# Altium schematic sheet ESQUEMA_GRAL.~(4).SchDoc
size A3
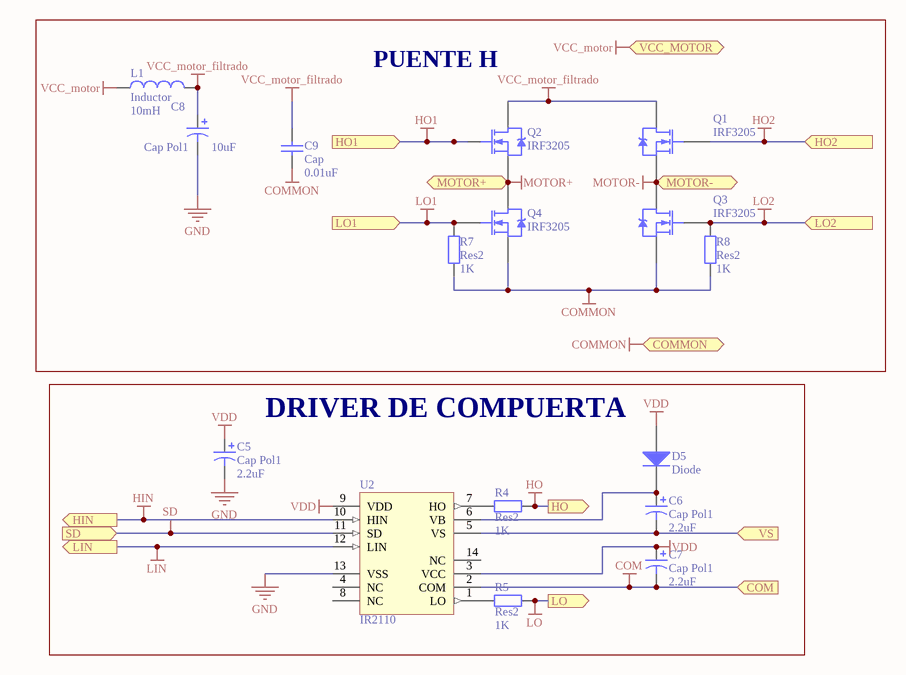
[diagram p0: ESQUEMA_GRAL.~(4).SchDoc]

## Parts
C5  Cap Pol1  value 2.2uF  [CAPPR2.5-6.3X5]
C6  Cap Pol1  value 2.2uF  [CAPPR2.5-6.3X5]
C7  Cap Pol1  value 2.2uF  [CAPPR2.5-6.3X5]
C8  Cap Pol1  value 10uF  [CAPPR5-13X16]
C9  Cap  value 0.01uF  [RAD-0.2]
D5  Diode  [DO-204AL]
L1  Inductor  value 10mH  [bobina_Choque]
Q1  IRF3205  [TO-220AB]
Q2  IRF3205  [TO-220AB]
Q3  IRF3205  [TO-220AB]
Q4  IRF3205  [TO-220AB]
R4  Res2  value 1K  [AXIAL-0.3]
R5  Res2  value 1K  [AXIAL-0.3]
R7  Res2  value 1K  [AXIAL-0.3]
R8  Res2  value 1K  [AXIAL-0.3]
U2  IR2110  [PDIP14]

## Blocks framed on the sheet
PUENTE H: C8 C9 L1 Q1-Q4 R7 R8
DRIVER DE COMPUERTA: C5-C7 D5 R4 R5 U2

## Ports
COM (in), COMMON (out), HIN (out), HO1 (in), HO2 (in), HO (out), LIN (out), LO1 (in), LO2 (in), LO (out), MOTOR+ (bidir), MOTOR- (bidir), SD (in), VCC_MOTOR (in), VS (in)

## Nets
COM: C7.2 U2.2(COM) ; port COM
COMMON: C9.1 Q3.3(S) Q4.3(S) R7.1 R8.1 ; port COMMON
GND: C5.2 C8.2 U2.13(VSS)
HIN: U2.10(HIN) ; port HIN
HO: R4.2 ; port HO
HO1: Q2.1(G) ; port HO1
HO2: Q1.1(G) ; port HO2
LIN: U2.12(LIN) ; port LIN
LO: R5.2 ; port LO
LO1: Q4.1(G) R7.2 ; port LO1
LO2: Q3.1(G) R8.2 ; port LO2
MOTOR+: Q2.3(S) Q4.2(D) ; port MOTOR+
MOTOR-: Q1.3(S) Q3.2(D) ; port MOTOR-
SD: U2.11(SD) ; port SD
VCC_motor: L1.1 ; port VCC_MOTOR
VCC_motor_filtrado: C8.1 C9.2 L1.2 Q1.2(D) Q2.2(D)
VDD: C5.1 C7.1 D5.1(A) U2.3(VCC) U2.9(VDD)
VS: C6.2 U2.5(VS) ; port VS
NetC6_1: C6.1 D5.2(K) U2.6(VB)
NetR4_1: R4.1 U2.7(HO)
NetR5_1: R5.1 U2.1(LO)

Not connected (* = marked no-connect by the designer): U2 4(NC) 8(NC) 14(NC)

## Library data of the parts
C5-C8 = Cap Pol1: Polarized Capacitor (Radial)
C9 = Cap: Capacitor
D5 = Diode: Default Diode
L1 = Inductor: Code_IEC: 1005
Q1-Q4 = IRF3205: HEXFET Power MOSFET; Note: Pin 2 is electrically connected to pin 4.
R4 R5 R7 R8 = Res2: Resistor
U2 = IR2110: High and Low Side Driver; Note: Pins 4, 8 and 14 are not connected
